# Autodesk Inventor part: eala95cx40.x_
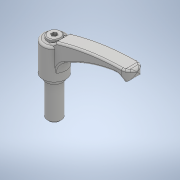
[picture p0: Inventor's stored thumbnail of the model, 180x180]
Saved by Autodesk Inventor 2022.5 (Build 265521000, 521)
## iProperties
Created: 2018-05
Part Number: eala95cx40.x_
Material: 一般
Document SubType Name: Modeling
Designer: imaocorp
Density: 1 g/cm^3
Appearance: 既定
Sending System: SOLIDWORKS 2016-2016286
MC: AMD64
MC_MODEL: AMD64 Family 21 Model 2 Stepping 0, AuthenticAMD
OS: Windows_NT
FRU: Parasolid Version 28.0, build 224,  7-29-2016
FORMAT: text
GUISE: transmit
KEY: eala95cx40
FILE: eala95cx40.x_t
DATE: Fri May 18 11:34:22 2018
Author: imaocorp
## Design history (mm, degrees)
feature "Base1"
node "ソリッド1"
